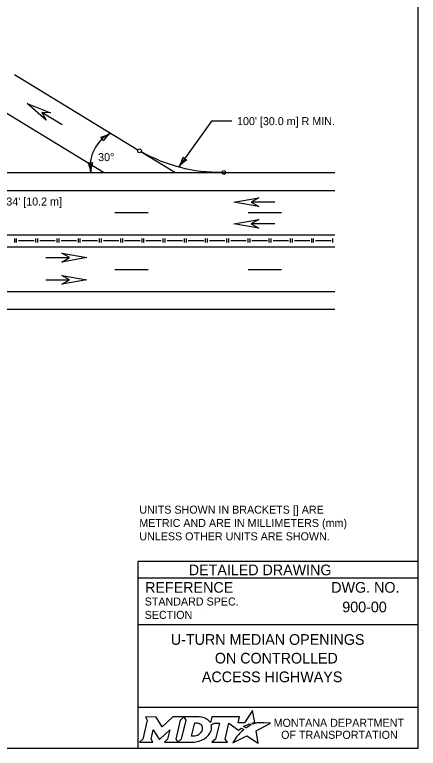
# Model space of a CAD drawing. Extents: x 49991.4 to 50021, y 49987.6 to 50011.4.
# Drawn here: x 50005.59 to 50008.61, y 50000.06 to 50005.56 of the extents above; entities that cross this region are included whole.
import ezdxf

# ---------------------------------------------------------------- set-up
doc = ezdxf.new("R2010")
doc.units = 0
for name, color, linetype in [('Level 1', 7, 'Continuous'), ('Level 2', 7, 'Continuous'), ('Level 3', 7, 'Continuous')]:
    doc.layers.add(name, color=color, linetype=linetype)

msp = doc.modelspace()

# ---------------------------------------------------------------- linework, layer by layer
at = {"layer": 'Level 1'}
for p, q in [((50006.5134, 50004.5478), (50005.5905, 50005.1118)), ((50006.2573, 50004.3784), (50005.4358, 50004.8804)), ((50005.9464, 50004.7356), (50005.7946, 50004.8284)), ((50006.7905, 50004.3784), (50006.5372, 50004.5332)), ((50001.1572, 50004.3784), (50007.9905, 50004.3784)), ((50001.1572, 50004.2451), (50007.9905, 50004.2451)), ((50007.5405, 50004.1562), (50007.3626, 50004.1562)), ((50006.3404, 50004.0784), (50006.5904, 50004.0784)), ((50007.3404, 50004.0784), (50007.5904, 50004.0784)), ((50007.5405, 50003.9936), (50007.3626, 50003.9936)), ((50001.1572, 50003.9118), (50007.9905, 50003.9118)), ((50005.5914, 50003.8548), (50005.5914, 50003.8836)), ((50005.6059, 50003.8548), (50005.6059, 50003.8836)), ((50005.7503, 50003.8548), (50005.7503, 50003.8836)), ((50005.7648, 50003.8548), (50005.7648, 50003.8836)), ((50005.9093, 50003.8548), (50005.9093, 50003.8836)), ((50005.9237, 50003.8548), (50005.9237, 50003.8836)), ((50006.0682, 50003.8548), (50006.0682, 50003.8836)), ((50006.0826, 50003.8548), (50006.0826, 50003.8836)), ((50006.2271, 50003.8548), (50006.2271, 50003.8836)), ((50006.2415, 50003.8548), (50006.2415, 50003.8836)), ((50006.386, 50003.8548), (50006.386, 50003.8836)), ((50006.4005, 50003.8548), (50006.4005, 50003.8836)), ((50006.5449, 50003.8548), (50006.5449, 50003.8836)), ((50006.5594, 50003.8548), (50006.5594, 50003.8836)), ((50006.7038, 50003.8548), (50006.7038, 50003.8836)), ((50006.7183, 50003.8548), (50006.7183, 50003.8836)), ((50006.8628, 50003.8548), (50006.8628, 50003.8836)), ((50006.8772, 50003.8548), (50006.8772, 50003.8836)), ((50007.0217, 50003.8548), (50007.0217, 50003.8836)), ((50007.0361, 50003.8548), (50007.0361, 50003.8836)), ((50007.1806, 50003.8548), (50007.1806, 50003.8836)), ((50007.195, 50003.8548), (50007.195, 50003.8836)), ((50007.3395, 50003.8548), (50007.3395, 50003.8836)), ((50007.3539, 50003.8548), (50007.3539, 50003.8836)), ((50007.4984, 50003.8548), (50007.4984, 50003.8836)), ((50007.5129, 50003.8548), (50007.5129, 50003.8836)), ((50007.6573, 50003.8548), (50007.6573, 50003.8836)), ((50007.6718, 50003.8548), (50007.6718, 50003.8836)), ((50007.8162, 50003.8548), (50007.8162, 50003.8836)), ((50007.8307, 50003.8548), (50007.8307, 50003.8836)), ((50007.9752, 50003.8548), (50007.9752, 50003.8836)), ((50007.9905, 50003.8192), (50001.1572, 50003.8192)), ((50005.8233, 50003.741), (50006.0012, 50003.741)), ((50006.3404, 50003.6525), (50006.5904, 50003.6525)), ((50007.3404, 50003.6525), (50007.5904, 50003.6525)), ((50005.8233, 50003.5746), (50006.0012, 50003.5746)), ((50007.9905, 50003.4859), (50001.1572, 50003.4859)), ((50007.9905, 50003.3525), (50001.1572, 50003.3525))]:
    msp.add_line(p, q, dxfattribs=at)
for points in [[(50008.6146, 50011.2628), (50000.3356, 50011.2628), (50000.3356, 50000.0624), (50008.6146, 50000.0624)], [(50005.826, 50004.7707), (50005.6843, 50004.8958), (50005.8604, 50004.8269), (50005.7947, 50004.8283)], [(50007.4195, 50004.1234), (50007.2333, 50004.1562), (50007.4195, 50004.1892), (50007.3627, 50004.1562)], [(50007.4195, 50003.9608), (50007.2333, 50003.9936), (50007.4195, 50004.0266), (50007.3627, 50003.9936)], [(50005.9443, 50003.774), (50006.1305, 50003.7412), (50005.9443, 50003.7082), (50006.0011, 50003.7412)], [(50005.9443, 50003.6076), (50006.1305, 50003.5748), (50005.9443, 50003.5418), (50006.0011, 50003.5748)]]:
    msp.add_lwpolyline(points, close=True, dxfattribs=at)
for points in [[(50005.6203, 50003.8692), (50005.7359, 50003.8692)], [(50005.7792, 50003.8692), (50005.8948, 50003.8692)], [(50005.9382, 50003.8692), (50006.0537, 50003.8692)], [(50006.0971, 50003.8692), (50006.2126, 50003.8692)], [(50006.256, 50003.8692), (50006.3716, 50003.8692)], [(50006.4149, 50003.8692), (50006.5305, 50003.8692)], [(50006.5738, 50003.8692), (50006.6894, 50003.8692)], [(50006.7327, 50003.8692), (50006.8483, 50003.8692)], [(50006.8916, 50003.8692), (50007.0072, 50003.8692)], [(50007.0506, 50003.8692), (50007.1661, 50003.8692)], [(50007.2095, 50003.8692), (50007.325, 50003.8692)], [(50007.3684, 50003.8692), (50007.484, 50003.8692)], [(50007.5273, 50003.8692), (50007.6429, 50003.8692)], [(50007.6862, 50003.8692), (50007.8018, 50003.8692)], [(50007.8451, 50003.8692), (50007.9607, 50003.8692)]]:
    msp.add_lwpolyline(points, dxfattribs=at)
for centre in [(50006.5261, 50004.5418), (50007.1574, 50004.3794)]:
    msp.add_circle(centre, 0.014, dxfattribs=at)
msp.add_arc((50007.1284, 50005.5809), 1.1993, 240.566, 270.7228, dxfattribs=at)
at = {"layer": 'Level 2'}
for p, q in [((50008.6146, 50001.4624), (50006.5146, 50001.4624)), ((50006.5146, 50001.4624), (50006.5146, 50000.0624)), ((50008.6146, 50001.3374), (50006.5146, 50001.3374)), ((50008.2507, 50001.1223), (50008.2507, 50001.1223)), ((50007.0089, 50001.0629), (50007.0089, 50001.0629)), ((50008.6146, 50000.9874), (50006.5146, 50000.9874)), ((50007.5646, 50000.7383), (50007.5646, 50000.7383)), ((50008.6146, 50000.3693), (50006.5146, 50000.3693))]:
    msp.add_line(p, q, dxfattribs=at)
for points in [[(50007.3771, 50000.2447), (50007.3668, 50000.2503), (50007.3784, 50000.2531), (50007.39, 50000.2551), (50007.3726, 50000.3452), (50007.3131, 50000.2539), (50007.2658, 50000.2532), (50007.2761, 50000.2973), (50007.0669, 50000.2974), (50007.0568, 50000.2549), (50007.051, 50000.2632)], [(50006.5701, 50000.2974), (50006.5842, 50000.274), (50006.5507, 50000.1307), (50006.525, 50000.1082), (50006.6266, 50000.1082), (50006.6131, 50000.131), (50006.6293, 50000.2011), (50006.673, 50000.1321), (50006.6783, 50000.1321), (50006.7534, 50000.2016), (50006.737, 50000.1305), (50006.7123, 50000.1085), (50006.8139, 50000.1085), (50006.8001, 50000.1318), (50006.8333, 50000.2742)], [(50006.8333, 50000.2742), (50006.8586, 50000.2974), (50006.7762, 50000.2974), (50006.6966, 50000.2244), (50006.6521, 50000.2971), (50006.5701, 50000.2974)], [(50006.9722, 50000.2974), (50006.8586, 50000.2974), (50006.8733, 50000.2745), (50006.8394, 50000.1307), (50006.8139, 50000.1085), (50006.9245, 50000.1085)], [(50006.9962, 50000.2107), (50006.995, 50000.2026), (50006.9918, 50000.1933), (50006.9876, 50000.1851), (50006.982, 50000.1776), (50006.9755, 50000.1707), (50006.9676, 50000.1644), (50006.9593, 50000.1597), (50006.9502, 50000.1558), (50006.9411, 50000.1535), (50006.9319, 50000.1526), (50006.916, 50000.1526), (50006.9396, 50000.2526), (50006.9556, 50000.2526), (50006.9632, 50000.252), (50006.9708, 50000.2501), (50006.9774, 50000.2471), (50006.9835, 50000.2429), (50006.9883, 50000.2379), (50006.992, 50000.2319), (50006.9947, 50000.2257), (50006.9963, 50000.2183), (50006.9963, 50000.2153), (50006.9962, 50000.2107)], [(50007.0636, 50000.2383), (50007.0882, 50000.2514), (50007.1251, 50000.2514), (50007.0965, 50000.1309), (50007.069, 50000.1082), (50007.1852, 50000.1082), (50007.1682, 50000.1311), (50007.1964, 50000.2513), (50007.2677, 50000.1996), (50007.2888, 50000.2147), (50007.3085, 50000.2038)], [(50007.2527, 50000.1479), (50007.2374, 50000.1235), (50007.2327, 50000.116), (50007.2269, 50000.1074), (50007.2246, 50000.1031), (50007.3299, 50000.1562), (50007.4138, 50000.1011), (50007.4007, 50000.1938), (50007.5076, 50000.2522), (50007.4583, 50000.253), (50007.4282, 50000.2534), (50007.4074, 50000.2537), (50007.4006, 50000.2522), (50007.3957, 50000.251), (50007.3873, 50000.2487), (50007.3771, 50000.2447)], [(50007.3267, 50000.2171), (50007.3243, 50000.2154), (50007.306, 50000.225), (50007.3163, 50000.2307), (50007.3204, 50000.2329), (50007.329, 50000.2369), (50007.3347, 50000.2395), (50007.3426, 50000.2425), (50007.3499, 50000.2452), (50007.3617, 50000.2378), (50007.3577, 50000.2357), (50007.3531, 50000.2332), (50007.3489, 50000.231), (50007.3439, 50000.2281), (50007.342, 50000.227), (50007.3393, 50000.2254), (50007.3368, 50000.224), (50007.3345, 50000.2224), (50007.3319, 50000.2206), (50007.3292, 50000.2188), (50007.3267, 50000.2171)], [(50006.9702, 50000.1158), (50006.9786, 50000.1184), (50006.9916, 50000.1238), (50007.012, 50000.1348)], [(50007.2666, 50000.164), (50007.2666, 50000.164)]]:
    msp.add_lwpolyline(points, dxfattribs=at)
for centre, radius, start, end in [((50006.9953, 50000.219), 0.0709, 339.5329, 15.8582), ((50006.9513, 50000.2363), 0.1183, 300.9103, 339.1383)]:
    msp.add_arc(centre, radius, start, end, dxfattribs=at)
for centre, major_axis, ratio, start_param, end_param in [((50006.9701, 50000.25), (0.0834, -0.0037), 0.568097, 0.61298, 1.570796), ((50007.0257, 50000.2573), (0.0361, -0.0295), 0.469099, 1.225588, 1.570796), ((50007.2764, 50000.1742), (-0.0098, -0.0102), 0.016458, 3.141593, 6.279097), ((50007.2974, 50000.1941), (-0.0112, -0.0097), 0.021651, 3.157348, 6.283185), ((50007.2597, 50000.1559), (-0.00694, -0.00806), 0.008222, 0, 3.137361), ((50006.9248, 50000.2568), (0, 0.1484), 0.987302, 3.139398, 3.456847)]:
    msp.add_ellipse(centre, major_axis=major_axis, ratio=ratio, start_param=start_param, end_param=end_param, dxfattribs=at)
at = {"layer": 'Level 3'}
for p, q in [((50007.0649, 50004.7644), (50006.8217, 50004.4215)), ((50007.2167, 50004.7644), (50007.0649, 50004.7644))]:
    msp.add_line(p, q, dxfattribs=at)
for centre, radius, start, end in [((50006.4306, 50004.429), 0.2734, 116.6428, 190.6586), ((50006.1898, 50004.8616), 0.2223, 281.9484, 302.1319), ((50006.2023, 50004.6007), 0.0548, 16.6312, 52.3536), ((50006.4493, 50004.488), 0.233, 127.3197, 146.5696), ((50006.6252, 50004.5467), 0.233, 327.4833, 346.7332), ((50006.9976, 50004.2855), 0.2223, 122.112, 142.2955), ((50006.8959, 50004.5261), 0.0548, 216.7948, 252.5172), ((50006.1553, 50004.5064), 0.0548, 255.1078, 290.8301), ((50005.9301, 50004.3549), 0.233, 5.7963, 25.0461), ((50006.3842, 50004.3808), 0.2223, 160.425, 180.6085)]:
    msp.add_arc(centre, radius, start, end, dxfattribs=at)

# ---------------------------------------------------------------- texts
at = {"layer": 'Level 2'}
for s, height, p in [("100' [30.0 m] R MIN.", 0.06, (50007.2567, 50004.7344)), ('30°', 0.06, (50006.2162, 50004.4646)), ("34' [10.2 m]", 0.06, (50005.5285, 50004.1318)), ('UNITS SHOWN IN BRACKETS [] ARE ', 0.06, (50006.5246, 50001.8218)), ('METRIC AND ARE IN MILLIMETERS (mm) ', 0.06, (50006.5246, 50001.7218)), ('UNLESS OTHER UNITS ARE SHOWN.', 0.06, (50006.5246, 50001.6218)), ('DETAILED DRAWING', 0.0799, (50006.8956, 50001.3599)), ('REFERENCE', 0.08, (50006.5682, 50001.229)), ('DWG. NO.', 0.08, (50007.9624, 50001.229)), ('STANDARD SPEC.', 0.06, (50006.5649, 50001.133)), ('900-00', 0.08, (50008.0451, 50001.0823)), ('SECTION', 0.06, (50006.5649, 50001.033)), ('U-TURN MEDIAN OPENINGS', 0.08, (50006.7608, 50000.8383)), ('ON CONTROLLED', 0.08, (50007.0903, 50000.6983)), ('ACCESS HIGHWAYS', 0.08, (50006.9933, 50000.5583)), ('MONTANA DEPARTMENT', 0.06, (50007.5308, 50000.2236)), ('OF TRANSPORTATION', 0.06, (50007.587, 50000.1336))]:
    msp.add_text(s, height=height, dxfattribs=at).set_placement(p)

doc.saveas('drawing.dxf')
